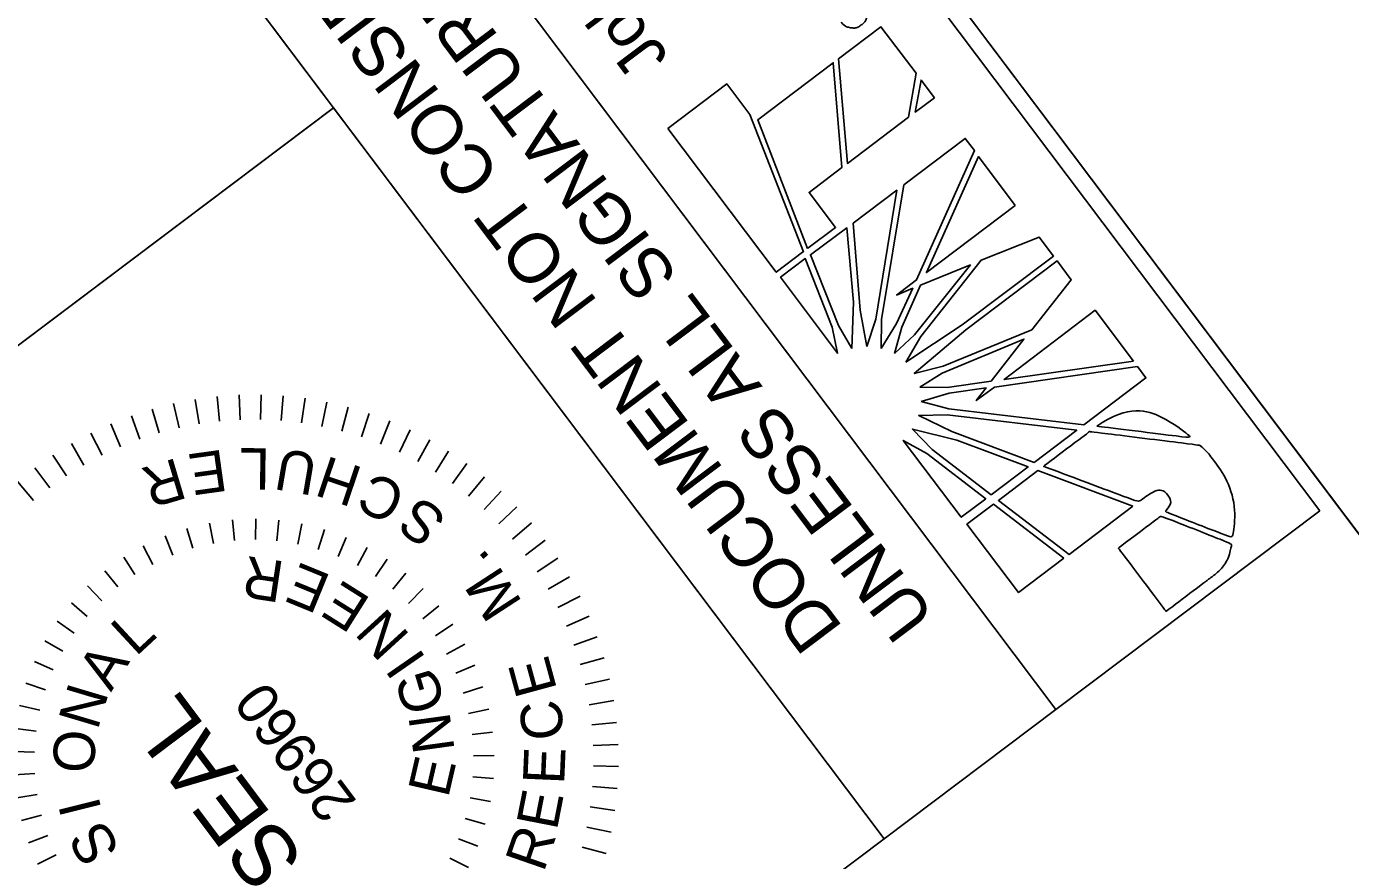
# Model space of a CAD drawing. Extents: x 1262749 to 1264921, y 774795 to 776798.
# Drawn here: x 1263207.9 to 1263352.6, y 776067.5 to 776158.6 of the extents above; entities that cross this region are included whole.
import ezdxf

# ---------------------------------------------------------------- set-up
doc = ezdxf.new("R2010")
doc.units = 0
for name, color, linetype in [('Default', 7, 'Continuous'), ('Sheet Border Standard 30in CELL', 7, 'Continuous'), ('Sheet Data Field CELL', 7, 'Continuous'), ('Sheet Layout Plan Border', 7, 'Continuous'), ('Sheet Plan Layout CELL', 7, 'Continuous')]:
    doc.layers.add(name, color=color, linetype=linetype)

# ---------------------------------------------------------------- blocks, each defined once
blk = doc.blocks.new('SEALNC2')
at = {"layer": 'Default'}
for p, q in [((0.1423, 0.4963), (0.1334, 0.4507)), ((0.1928, 0.4838), (0.1796, 0.4393)), ((0.242, 0.4665), (0.2244, 0.4235)), ((0.2892, 0.4445), (0.2676, 0.4034)), ((0.334, 0.4181), (0.3086, 0.3792)), ((0.3761, 0.3874), (0.347, 0.3512)), ((0.415, 0.3529), (0.3825, 0.3196)), ((0.4505, 0.3147), (0.415, 0.2848)), ((0.4821, 0.2734), (0.4438, 0.2469)), ((0.5094, 0.2291), (0.4689, 0.2065)), ((0.5325, 0.1824), (0.4899, 0.1639)), ((0.5509, 0.1337), (0.5067, 0.1194)), ((0.5646, 0.0834), (0.5192, 0.0735)), ((0.5733, 0.0321), (0.5272, 0.0266)), ((0.8544, 0.0163), (0.7988, 0.013)), ((0.577, -0.0198), (0.5306, -0.0209)), ((0.8558, -0.0331), (0.8001, -0.033)), ((0.5757, -0.0719), (0.5294, -0.0685)), ((0.8543, -0.0825), (0.7987, -0.0791)), ((0.5239, -0.1141), (0.5697, -0.1218)), ((0.8498, -0.1316), (0.7945, -0.1249)), ((0.5581, -0.1744), (0.5133, -0.1622)), ((0.8423, -0.1804), (0.7876, -0.1704)), ((0.5419, -0.2239), (0.4986, -0.2074)), ((0.8319, -0.2287), (0.7778, -0.2154)), ((-0.4448, -0.2707), (-0.4033, -0.2501)), ((0.5211, -0.2716), (0.4795, -0.2509)), ((0.8186, -0.2763), (0.7654, -0.2597)), ((-0.4197, -0.3162), (-0.3802, -0.2918)), ((0.4958, -0.317), (0.4563, -0.2926)), ((0.8025, -0.3229), (0.7504, -0.3031)), ((-0.3901, -0.3591), (-0.3531, -0.331)), ((0.4662, -0.3599), (0.4293, -0.3317)), ((0.7835, -0.3685), (0.7327, -0.3457)), ((-0.3565, -0.3989), (-0.3225, -0.3674)), ((0.4325, -0.3996), (0.3986, -0.368)), ((-0.3194, -0.4353), (-0.2885, -0.4006)), ((0.3953, -0.436), (0.3645, -0.4012)), ((0.7619, -0.4129), (0.7125, -0.387)), ((-0.2788, -0.4679), (-0.2515, -0.4304)), ((0.3546, -0.4685), (0.3274, -0.4309)), ((0.7376, -0.456), (0.6899, -0.427)), ((-0.2353, -0.4965), (-0.2116, -0.4565)), ((0.3111, -0.497), (0.2875, -0.4569)), ((0.7107, -0.4974), (0.6649, -0.4657)), ((-0.6057, -0.5359), (-0.5618, -0.5016)), ((-0.1891, -0.5207), (-0.1695, -0.4786)), ((-0.1409, -0.5405), (-0.1255, -0.4966)), ((0.2166, -0.5408), (0.2013, -0.4969)), ((0.2649, -0.5211), (0.2454, -0.479)), ((0.6814, -0.5371), (0.6376, -0.5027)), ((-0.0802, -0.5102), (-0.0914, -0.5553)), ((-0.04, -0.5654), (-0.0333, -0.5195)), ((0.0118, -0.5705), (0.014, -0.5241)), ((0.0638, -0.5706), (0.0617, -0.5242)), ((0.1157, -0.5656), (0.109, -0.5196)), ((0.1668, -0.5556), (0.1557, -0.5105)), ((-0.5741, -0.5739), (-0.5323, -0.537)), ((0.6497, -0.575), (0.6081, -0.538)), ((-0.5402, -0.6098), (-0.5008, -0.5705)), ((0.6158, -0.6109), (0.5765, -0.5715)), ((-0.5044, -0.6437), (-0.4674, -0.6021)), ((0.5799, -0.6447), (0.543, -0.603)), ((-0.4664, -0.6754), (-0.432, -0.6316)), ((0.5419, -0.6764), (0.5076, -0.6325)), ((-0.4267, -0.7047), (-0.395, -0.6589)), ((0.5021, -0.7056), (0.4705, -0.6597)), ((-0.3853, -0.7316), (-0.3563, -0.6839)), ((-0.3422, -0.7559), (-0.3163, -0.7065)), ((0.4176, -0.7566), (0.3917, -0.7072)), ((0.4607, -0.7323), (0.4318, -0.6847)), ((-0.2978, -0.7775), (-0.275, -0.7267)), ((0.3731, -0.7781), (0.3504, -0.7273)), ((-0.2523, -0.7965), (-0.2324, -0.7444)), ((-0.2056, -0.8127), (-0.189, -0.7594)), ((-0.158, -0.8259), (-0.1447, -0.7719)), ((0.2809, -0.8131), (0.2643, -0.7598)), ((0.3275, -0.797), (0.3078, -0.7449)), ((-0.1098, -0.8364), (-0.0997, -0.7816)), ((-0.061, -0.8438), (-0.0542, -0.7885)), ((-0.0118, -0.8483), (-0.0084, -0.7927)), ((0.0376, -0.8498), (0.0376, -0.7941)), ((0.087, -0.8484), (0.0837, -0.7928)), ((0.1361, -0.8439), (0.1295, -0.7887)), ((0.1849, -0.8366), (0.175, -0.7818)), ((0.2332, -0.8263), (0.22, -0.7722))]:
    blk.add_line(p, q, dxfattribs=at)
for s, height, rotation, p in [('S', 0.0928, 352.2989, (0.0548, 0.3282)), ('I', 0.0928, 337.0026, (0.1534, 0.3081)), ('O', 0.0928, 321.7064, (0.2282, 0.2719)), ('N', 0.0928, 306.4101, (0.2997, 0.2096)), ('SEAL', 0.1393, 359.947, (-0.2112, 0.0097)), ('A', 0.0928, 291.1139, (0.3505, 0.1336)), ('L', 0.0928, 275.8176, (0.3804, 0.0417)), ('26960', 0.09279, 359.947, (-0.1777, -0.1611)), ('R', 0.0928, 69.6194, (0.6822, -0.3019)), ('R', 0.0928, 44.5119, (0.3489, -0.356)), ('E', 0.0928, 310.0171, (-0.2945, -0.3268)), ('E', 0.0928, 60.9466, (0.6344, -0.3956)), ('E', 0.0928, 30.7408, (0.2604, -0.4206)), ('R', 0.0928, 303.882, (-0.5567, -0.3975)), ('N', 0.0928, 330.8721, (-0.2167, -0.4042)), ('E', 0.0928, 20.7549, (0.1652, -0.4601)), ('G', 0.0928, 339.6384, (-0.1259, -0.4478)), ('I', 0.0928, 357.7332, (-0.0154, -0.4776)), ('N', 0.0928, 5.3628, (0.0476, -0.4808)), ('L', 0.0928, 52.154, (0.573, -0.481)), ('E', 0.0928, 311.9538, (-0.4993, -0.4777)), ('U', 0.0928, 43.2714, (0.4951, -0.5602)), ('E', 0.0928, 320.5966, (-0.4263, -0.5534)), ('H', 0.0928, 34.3888, (0.4105, -0.6228)), ('C', 0.0928, 329.2691, (-0.3427, -0.6173)), ('C', 0.0928, 25.5662, (0.3136, -0.6738)), ('E', 0.0928, 338.2416, (-0.2464, -0.6697)), ('S', 0.0928, 16.5636, (0.2098, -0.709)), ('M', 0.0928, 356.0369, (-0.0442, -0.7258)), ('.', 0.0928, 3.7793, (0.077, -0.7288))]:
    blk.add_text(s, height=height, rotation=rotation, dxfattribs=at).set_placement(p)

msp = doc.modelspace()

# ---------------------------------------------------------------- linework, layer by layer
at = {"layer": 'Default'}
for p, q in [((1263200.09, 776243.7), (1263320.41, 776083.96)), ((1263301.64, 776069.83), (1263181.33, 776229.56)), ((1263320.41, 776083.96), (1263301.64, 776069.83))]:
    msp.add_line(p, q, dxfattribs=at)
at = {"layer": 'Sheet Border Standard 30in CELL'}
msp.add_line((1263151.63, 776082.06), (1263241.42, 776149.69), dxfattribs=at)
for points in [[(1263151.63, 776082.06), (1263091.48, 776161.91), (1263181.32, 776229.57), (1263241.46, 776149.72)], [(1263211.81, 776002.16), (1263151.63, 776082.06), (1263241.46, 776149.72), (1263301.64, 776069.83)]]:
    msp.add_lwpolyline(points, close=True, dxfattribs=at)
at = {"layer": 'Sheet Data Field CELL'}
for p, q in [((1263301.29, 776158.56), (1263296.66, 776155.06)), ((1263305.12, 776153.49), (1263301.29, 776158.56)), ((1263296.08, 776154.63), (1263287.83, 776148.4)), ((1263297.01, 776143.18), (1263296.08, 776154.63)), ((1263296.66, 776155.06), (1263297.63, 776143.64)), ((1263304.31, 776148.69), (1263305.12, 776153.49)), ((1263284.43, 776152.32), (1263277.99, 776147.46)), ((1263286.95, 776148.98), (1263284.43, 776152.32)), ((1263305.68, 776152.75), (1263305.04, 776149.24)), ((1263307.14, 776150.82), (1263305.68, 776152.75)), ((1263305.04, 776149.24), (1263307.14, 776150.82)), ((1263292.82, 776133.99), (1263286.95, 776148.98)), ((1263297.63, 776143.64), (1263304.31, 776148.69)), ((1263277.99, 776147.46), (1263289.85, 776131.75)), ((1263287.83, 776148.4), (1263293.26, 776134.33)), ((1263310.5, 776146.36), (1263303.8, 776141.29)), ((1263311.5, 776145.04), (1263310.5, 776146.36)), ((1263305.18, 776130.9), (1263311.5, 776145.04)), ((1263311.93, 776144.39), (1263306.25, 776131.71)), ((1263315.97, 776139.04), (1263311.93, 776144.39)), ((1263293.43, 776140.47), (1263297.01, 776143.18)), ((1263296.32, 776136.64), (1263293.43, 776140.47)), ((1263303.02, 776140.71), (1263298.24, 776137.1)), ((1263300.71, 776126.62), (1263303.02, 776140.71)), ((1263303.8, 776141.29), (1263301.33, 776126.56)), ((1263306.25, 776131.71), (1263315.97, 776139.04)), ((1263298.24, 776137.1), (1263299, 776127.59)), ((1263293.31, 776134.37), (1263296.32, 776136.64)), ((1263297.57, 776136.59), (1263293.58, 776133.66)), ((1263298.29, 776128.47), (1263297.57, 776136.59)), ((1263318.58, 776135.58), (1263312.23, 776133.05)), ((1263320.15, 776133.51), (1263318.58, 776135.58)), ((1263293.26, 776134.33), (1263293.31, 776134.37)), ((1263289.85, 776131.75), (1263292.73, 776133.93)), ((1263293.01, 776133.23), (1263290.32, 776131.2)), ((1263292.73, 776133.93), (1263292.82, 776133.99)), ((1263295.94, 776125.73), (1263293.01, 776133.23)), ((1263293.58, 776133.66), (1263296.64, 776125.93)), ((1263312.23, 776133.05), (1263305.65, 776124.71)), ((1263310.18, 776125.99), (1263320.15, 776133.51)), ((1263320.55, 776132.98), (1263310.58, 776125.46)), ((1263322.09, 776130.93), (1263320.55, 776132.98)), ((1263304.97, 776124.92), (1263311.06, 776132.55)), ((1263311.06, 776132.55), (1263305.62, 776130.32)), ((1263290.32, 776131.2), (1263296.54, 776122.89)), ((1263303, 776129.25), (1263305.18, 776130.9)), ((1263303, 776126.14), (1263304.76, 776129.99)), ((1263304.76, 776129.99), (1263303, 776129.25)), ((1263305.62, 776130.32), (1263303.57, 776125.74)), ((1263317.76, 776125.46), (1263322.09, 776130.93)), ((1263298.09, 776123.4), (1263298.29, 776128.47)), ((1263299, 776127.59), (1263299.74, 776123.62)), ((1263324.68, 776127.58), (1263314.75, 776120.01)), ((1263328.88, 776122.01), (1263324.68, 776127.58)), ((1263296.54, 776122.89), (1263295.94, 776125.73)), ((1263296.64, 776125.93), (1263298.09, 776123.4)), ((1263299.74, 776123.62), (1263300.71, 776126.62)), ((1263301.33, 776126.56), (1263301.3, 776123.42)), ((1263301.3, 776123.42), (1263303, 776126.14)), ((1263303.57, 776125.74), (1263302.76, 776122.87)), ((1263304, 776121.92), (1263310.18, 776125.99)), ((1263310.58, 776125.46), (1263304.93, 776120.69)), ((1263308.09, 776121.47), (1263317.76, 776125.46)), ((1263302.76, 776122.87), (1263304.97, 776124.92)), ((1263305.65, 776124.71), (1263304, 776121.92)), ((1263316.91, 776124.43), (1263307.99, 776120.73)), ((1263313.33, 776119.85), (1263316.91, 776124.43)), ((1263304.93, 776120.69), (1263308.09, 776121.47)), ((1263329.32, 776121.43), (1263313.68, 776119.2)), ((1263314.75, 776120.01), (1263328.88, 776122.01)), ((1263330.25, 776120.19), (1263329.32, 776121.43)), ((1263307.99, 776120.73), (1263305.53, 776119.2)), ((1263308.54, 776119.16), (1263313.33, 776119.85)), ((1263323.47, 776115.08), (1263330.25, 776120.19)), ((1263305.53, 776119.2), (1263308.54, 776119.16)), ((1263308.75, 776118.52), (1263305.67, 776117.63)), ((1263312.78, 776119.11), (1263308.75, 776118.52)), ((1263313.68, 776119.2), (1263311.71, 776117.71)), ((1263311.71, 776117.71), (1263312.78, 776119.11)), ((1263305.67, 776117.63), (1263308.7, 776116.8)), ((1263308.7, 776116.8), (1263323.47, 776115.08)), ((1263308.53, 776116.17), (1263305.42, 776116.09)), ((1263305.42, 776116.09), (1263309.02, 776114.33)), ((1263322.68, 776114.48), (1263308.53, 776116.17)), ((1263309.58, 776113.4), (1263304.73, 776114.6)), ((1263304.73, 776114.6), (1263306.87, 776112.38)), ((1263309.02, 776114.33), (1263318.02, 776110.96)), ((1263318.02, 776110.96), (1263322.68, 776114.48)), ((1263306.29, 776111.94), (1263303.72, 776113.37)), ((1263303.72, 776113.37), (1263310.07, 776104.96)), ((1263317.37, 776110.47), (1263309.58, 776113.4)), ((1263312.74, 776106.98), (1263306.29, 776111.94)), ((1263306.87, 776112.38), (1263313.32, 776107.42)), ((1263313.32, 776107.42), (1263317.37, 776110.47)), ((1263318.44, 776110.06), (1263314.12, 776106.8)), ((1263328.82, 776106.17), (1263318.44, 776110.06)), ((1263310.07, 776104.96), (1263312.74, 776106.98)), ((1263314.12, 776106.8), (1263321.85, 776100.91)), ((1263313.57, 776106.39), (1263310.69, 776104.21)), ((1263321.28, 776100.48), (1263313.57, 776106.39)), ((1263321.85, 776100.91), (1263328.82, 776106.17)), ((1263310.69, 776104.21), (1263316.33, 776096.74)), ((1263316.33, 776096.74), (1263321.28, 776100.48))]:
    msp.add_line(p, q, dxfattribs=at)
msp.add_lwpolyline([(1263349.24, 776105.68), (1263228.9, 776265.45), (1263200.06, 776243.74), (1263320.41, 776083.96)], close=True, dxfattribs=at)
for points in [[(1263297.63, 776143.64), (1263304.31, 776148.69), (1263305.12, 776153.49), (1263301.29, 776158.56), (1263296.66, 776155.06), (1263297.63, 776143.64), (1263297.63, 776143.64)], [(1263293.26, 776134.33), (1263293.31, 776134.37), (1263296.32, 776136.64), (1263293.43, 776140.47), (1263297.01, 776143.18), (1263296.08, 776154.63), (1263287.83, 776148.4), (1263293.26, 776134.33)], [(1263277.99, 776147.46), (1263289.85, 776131.75), (1263292.73, 776133.93), (1263292.82, 776133.99), (1263286.95, 776148.98), (1263284.43, 776152.32), (1263277.99, 776147.46)], [(1263307.14, 776150.82), (1263307.14, 776150.82), (1263305.68, 776152.75), (1263305.04, 776149.24), (1263307.14, 776150.82)], [(1263301.3, 776123.42), (1263303, 776126.14), (1263304.76, 776129.99), (1263303, 776129.25), (1263305.18, 776130.9), (1263311.5, 776145.04), (1263310.5, 776146.36), (1263303.8, 776141.29), (1263301.33, 776126.56), (1263301.3, 776123.42)], [(1263315.97, 776139.04), (1263311.93, 776144.39), (1263306.25, 776131.71), (1263315.97, 776139.04)], [(1263299.74, 776123.62), (1263300.71, 776126.62), (1263303.02, 776140.71), (1263298.24, 776137.1), (1263299, 776127.59), (1263299.74, 776123.62)], [(1263298.09, 776123.4), (1263298.29, 776128.47), (1263297.57, 776136.59), (1263293.58, 776133.66), (1263296.64, 776125.93), (1263298.09, 776123.4)], [(1263304, 776121.92), (1263310.18, 776125.99), (1263320.15, 776133.51), (1263318.58, 776135.58), (1263312.23, 776133.05), (1263305.65, 776124.71), (1263304, 776121.92)], [(1263295.94, 776125.73), (1263293.01, 776133.23), (1263290.32, 776131.2), (1263296.54, 776122.89), (1263295.94, 776125.73)], [(1263308.09, 776121.47), (1263317.76, 776125.46), (1263322.09, 776130.93), (1263320.55, 776132.98), (1263310.58, 776125.46), (1263304.93, 776120.69), (1263308.09, 776121.47)], [(1263302.76, 776122.87), (1263304.97, 776124.92), (1263311.06, 776132.55), (1263305.62, 776130.32), (1263303.57, 776125.74), (1263302.76, 776122.87)], [(1263328.88, 776122.01), (1263324.68, 776127.58), (1263314.75, 776120.01), (1263328.88, 776122.01)], [(1263305.53, 776119.2), (1263308.54, 776119.16), (1263313.33, 776119.85), (1263316.91, 776124.43), (1263307.99, 776120.73), (1263305.53, 776119.2)], [(1263305.67, 776117.63), (1263308.7, 776116.8), (1263323.47, 776115.08), (1263330.25, 776120.19), (1263329.32, 776121.43), (1263313.68, 776119.2), (1263311.71, 776117.71), (1263312.78, 776119.11), (1263308.75, 776118.52), (1263305.67, 776117.63)], [(1263318.02, 776110.96), (1263322.68, 776114.48), (1263308.53, 776116.17), (1263305.42, 776116.09), (1263309.02, 776114.33), (1263318.02, 776110.96)], [(1263313.32, 776107.42), (1263317.37, 776110.47), (1263309.58, 776113.4), (1263304.73, 776114.6), (1263306.87, 776112.38), (1263313.32, 776107.42)], [(1263306.29, 776111.94), (1263303.72, 776113.37), (1263310.07, 776104.96), (1263312.74, 776106.98), (1263306.29, 776111.94)], [(1263328.82, 776106.17), (1263318.44, 776110.06), (1263314.12, 776106.8), (1263321.85, 776100.91), (1263328.82, 776106.17)], [(1263321.28, 776100.48), (1263313.57, 776106.39), (1263310.69, 776104.21), (1263316.33, 776096.74), (1263321.28, 776100.48)]]:
    msp.add_lwpolyline(points, dxfattribs=at)
for points in [[(1263299.45, 776160.99), (1263299.7, 776160.65), (1263299.81, 776160.25), (1263299.75, 776159.81), (1263299.7, 776159.38), (1263299.49, 776159.03), (1263299.14, 776158.77), (1263298.78, 776158.5), (1263298.39, 776158.4), (1263297.97, 776158.47), (1263297.54, 776158.54), (1263297.2, 776158.74), (1263296.93, 776159.09)], [(1263324.88, 776114.92), (1263324.88, 776114.92), (1263335.28, 776113.63), (1263335.28, 776113.63), (1263332.43, 776115.95), (1263328.4, 776117.36), (1263324.88, 776114.92)], [(1263332.65, 776107.37), (1263332.98, 776106.93), (1263333.03, 776106.36), (1263332.32, 776105.58), (1263332.32, 776105.58), (1263339.68, 776102.72), (1263339.68, 776102.72), (1263340.18, 776105.68), (1263339.22, 776109.1), (1263337.54, 776111.33), (1263337.1, 776111.91), (1263336.72, 776112.32), (1263336.13, 776112.84), (1263336.13, 776112.84), (1263324.09, 776114.33), (1263324.09, 776114.33), (1263324.09, 776114.33), (1263319.06, 776110.53), (1263319.06, 776110.53), (1263319.06, 776110.53), (1263329.45, 776106.64), (1263329.45, 776106.64), (1263331.33, 776108.06), (1263332.18, 776107.99), (1263332.65, 776107.37)], [(1263332.65, 776107.37), (1263332.98, 776106.93), (1263333.03, 776106.36), (1263332.32, 776105.58), (1263332.32, 776105.58), (1263339.68, 776102.72), (1263339.68, 776102.72), (1263340.18, 776105.68), (1263339.22, 776109.1), (1263337.54, 776111.33), (1263337.1, 776111.91), (1263336.72, 776112.32), (1263336.13, 776112.84), (1263336.13, 776112.84), (1263324.09, 776114.33), (1263324.09, 776114.33), (1263324.09, 776114.33), (1263319.06, 776110.53), (1263319.06, 776110.53), (1263319.06, 776110.53), (1263329.45, 776106.64), (1263329.45, 776106.64), (1263331.33, 776108.06), (1263332.18, 776107.99), (1263332.65, 776107.37)], [(1263327.23, 776101.6), (1263327.23, 776101.6), (1263332.45, 776094.68), (1263332.45, 776094.68), (1263332.45, 776094.68), (1263336.78, 776097.95), (1263336.78, 776097.95), (1263336.78, 776097.95), (1263337.24, 776098.3), (1263337.24, 776098.3), (1263338.59, 776099.32), (1263339.33, 776100.57), (1263339.63, 776102.04), (1263339.63, 776102.04), (1263331.89, 776105.12), (1263331.81, 776105.05), (1263331.81, 776105.05), (1263327.23, 776101.6), (1263327.23, 776101.6)]]:
    msp.add_open_spline(points, degree=3, dxfattribs=at)
at = {"layer": 'Sheet Layout Plan Border'}
msp.add_lwpolyline([(1264772.58, 775612.83), (1263930.27, 776731.11), (1263260.5, 776226.63), (1263374.36, 776075.45), (1263205.44, 775948.22), (1263933.87, 774981.11)], close=True, dxfattribs=at)
at = {"layer": 'Sheet Plan Layout CELL'}
for points in [[(1263963.99, 774941.16), (1264802.66, 775572.89), (1263900.2, 776771.04), (1263230.42, 776266.56), (1263374.36, 776075.45), (1263205.44, 775948.22)], [(1263374.36, 776075.45), (1263230.41, 776266.58), (1263061.46, 776139.36), (1263205.44, 775948.22)]]:
    msp.add_lwpolyline(points, close=True, dxfattribs=at)

# ---------------------------------------------------------------- block references
at = {"layer": 'Default', "xscale": 48.735525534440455, "yscale": 48.73552553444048, "rotation": 126.9874160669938}
msp.add_blockref('SEALNC2', (1263232.62, 776076.08), dxfattribs=at)

# ---------------------------------------------------------------- texts
at = {"layer": 'Default'}
for s, p in [('UNLESS ALL SIGNATURES COMPLETED', (1263307.31, 776094.12)), ('DOCUMENT NOT CONSIDERED FINAL', (1263297.23, 776092.88))]:
    msp.add_text(s, height=5.4984, rotation=126.9874, dxfattribs=at).set_placement(p)
at = {"layer": 'Sheet Data Field CELL'}
msp.add_text('Johnson, Mirmiran, & Thompson Inc.', height=5.1112, rotation=126.9874, dxfattribs=at).set_placement((1263278.23, 776155.32))

doc.saveas('drawing.dxf')
